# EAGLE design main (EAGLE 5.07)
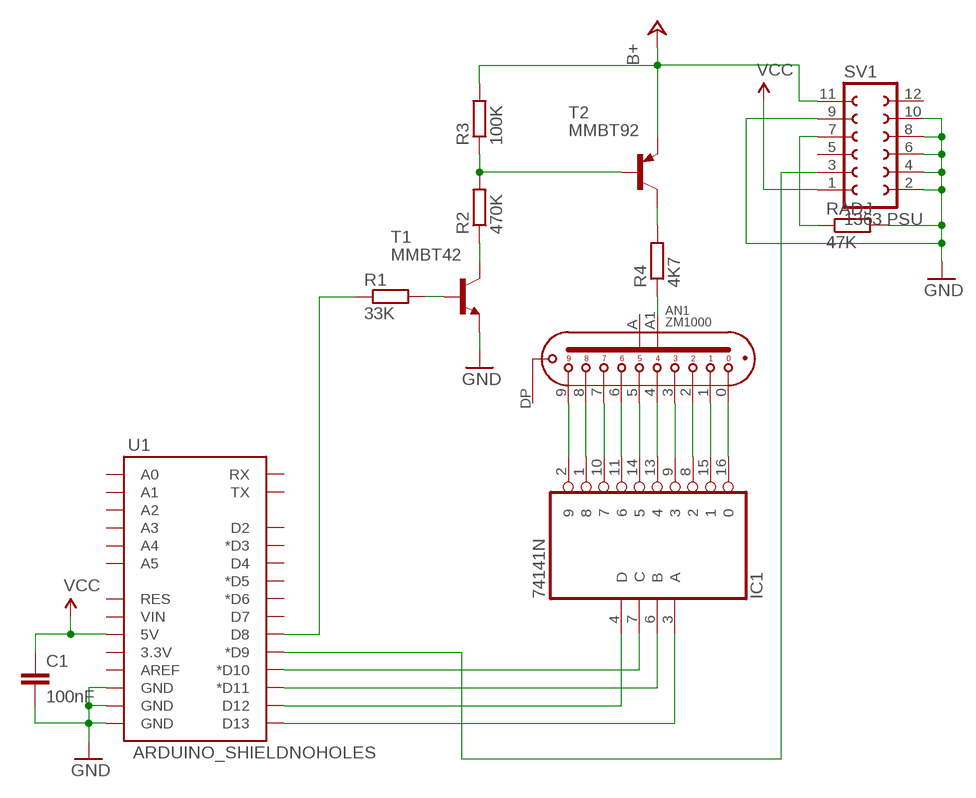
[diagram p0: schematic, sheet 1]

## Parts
AN1  ZM1000  [ZM1000]
C1  100nF  C-EUC0805  [C0805]
IC1  74141N  [DIL16]
R1  33K  R-EU_R0805  [R0805]
R2  470K  R-EU_R0805  [R0805]
R3  100K  R-EU_R0805  [R0805]
R4  4K7  R-EU_R0805  [R0805]
RADJ  47K  R-EU_R0805  [R0805]
SV1  1363 PSU  FE06-2  [FE06-2]
T1  MMBT42  MMBT918LT1-NPN-SOT23-BEC  [SOT23-BEC]
T2  MMBT92  MMBT4403LT1-PNP-SOT23-BEC  [SOT23-BEC]
U1  ARDUINO_SHIELDNOHOLES  [DUEMILANOVE_SHIELD_NOHOLES]

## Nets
+24V: R3.2 SV1.11 T2.E ; supply symbol labelled B+
GND: C1.2 RADJ.2 SV1.2 SV1.4 SV1.6 SV1.8 SV1.9 SV1.10 T1.E U1.GND@0(GND) U1.GND@1(GND) U1.GND@2(GND)
N$1: AN1.A1(A2) R4.1
N$2: SV1.3 U1.D9(*D9)
N$3: R4.2 T2.C
N$4: R2.2 R3.1 T2.B
N$5: R2.1 T1.C
N$6: R1.2 T1.B
N$7: AN1.0 IC1.16
N$8: AN1.1 IC1.15
N$9: AN1.2 IC1.8
N$10: AN1.3 IC1.9
N$11: AN1.4 IC1.13
N$12: AN1.5 IC1.14
N$13: AN1.6 IC1.11
N$14: AN1.7 IC1.10
N$15: AN1.8 IC1.1
N$16: AN1.9 IC1.2
N$17: IC1.3(A) U1.D13
N$18: IC1.4(D) U1.D12
N$19: IC1.6(B) U1.D11(*D11)
N$20: IC1.7(C) U1.D10(*D10)
N$21: R1.1 U1.D8
N$22: RADJ.1 SV1.7
VCC: C1.1 SV1.1 U1.5V
Unconnected: AN1.A(A1) AN1.DP(DPL) SV1.5 SV1.12 U1.3.3V U1.A0 U1.A1 U1.A2 U1.A3 U1.A4 U1.A5 U1.AREF U1.D2 U1.D3(*D3) U1.D4 U1.D5(*D5) U1.D6(*D6) U1.D7 U1.RES U1.RX U1.TX U1.VIN

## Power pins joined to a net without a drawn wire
GND: IC1.12(GND)
VCC: IC1.5(VCC)

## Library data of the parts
AN1 = nixie_tube:ZM1000: Indicator Tube (numeral height 14mm, no filter, side view, long-life typ)
C1 = rcl:C-EU: CAPACITOR, European symbol
IC1 = 74xx-eu:74*141: BCD to decimal DECODER/DRIVER
R1-R4 RADJ = rcl:R-EU_: RESISTOR, European symbol
SV1 = con-lsta:FE06-2: FEMALE HEADER
T1 = transistor:*-NPN-: NPN Transistror BF959 corrected 2008.03.06
T2 = transistor-neu-to92:*-PNP-: PNP Transistror
U1 = zapro:ARDUINO_SHIELD

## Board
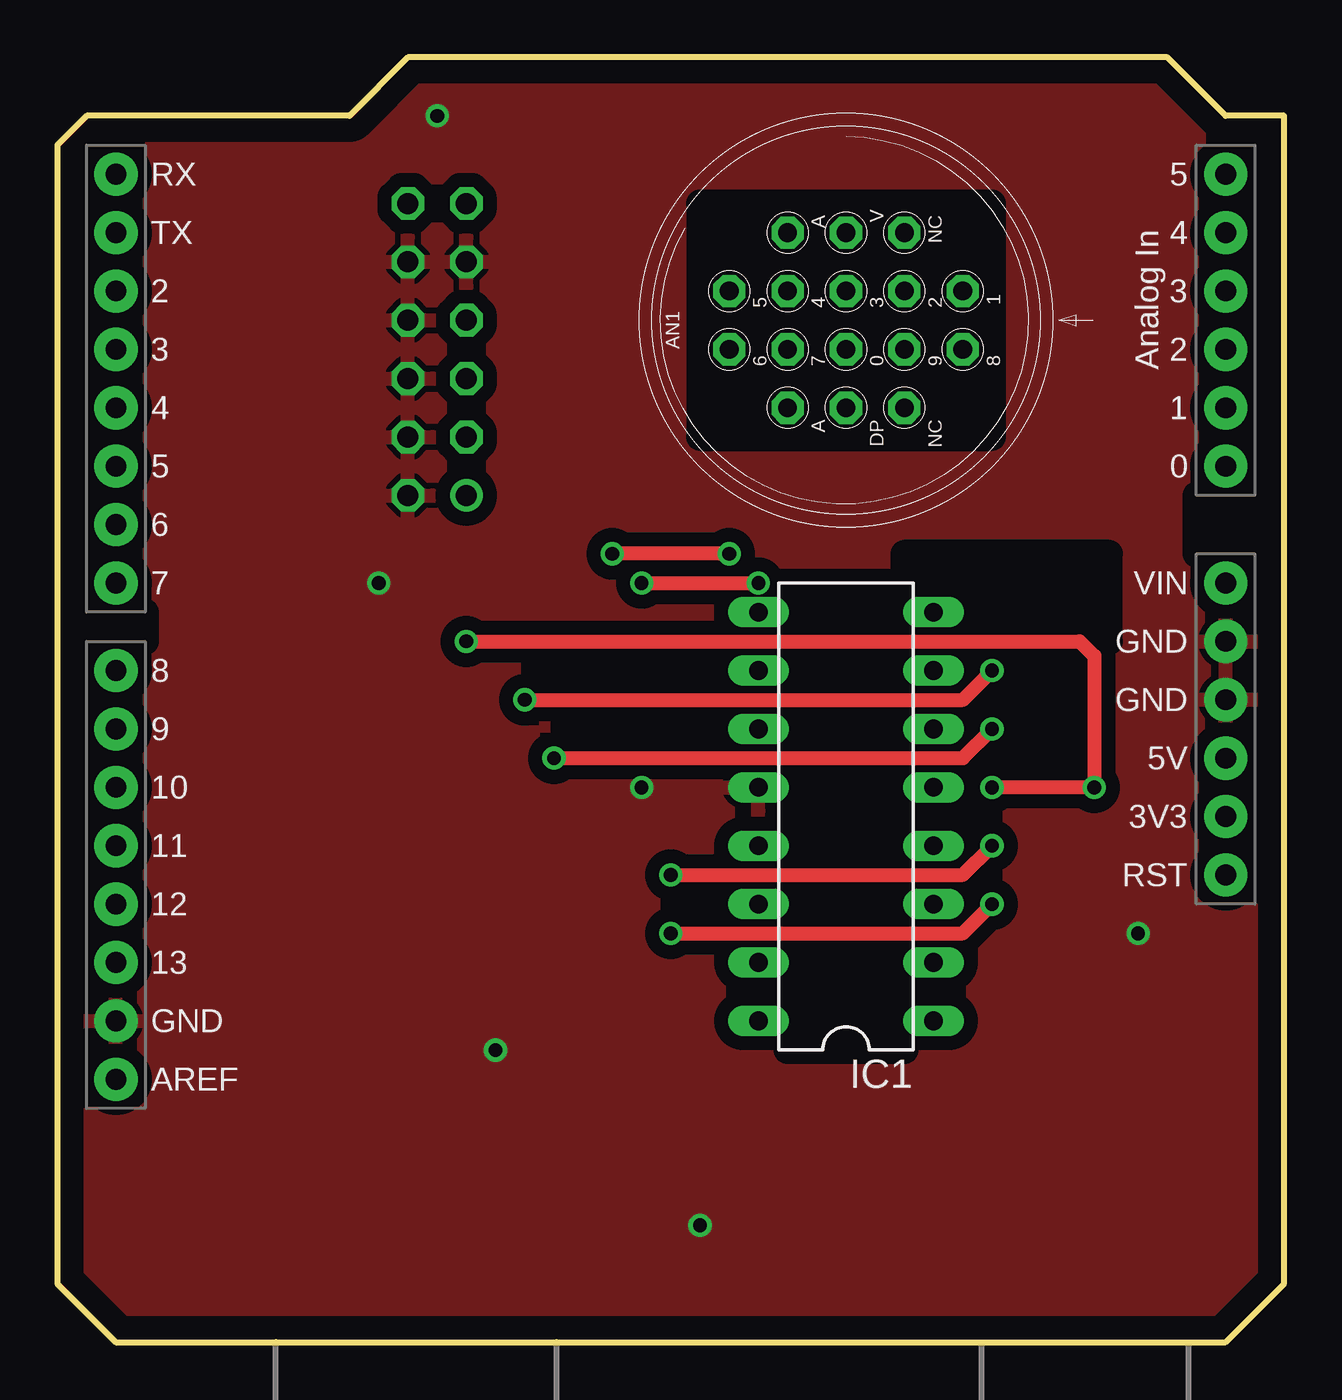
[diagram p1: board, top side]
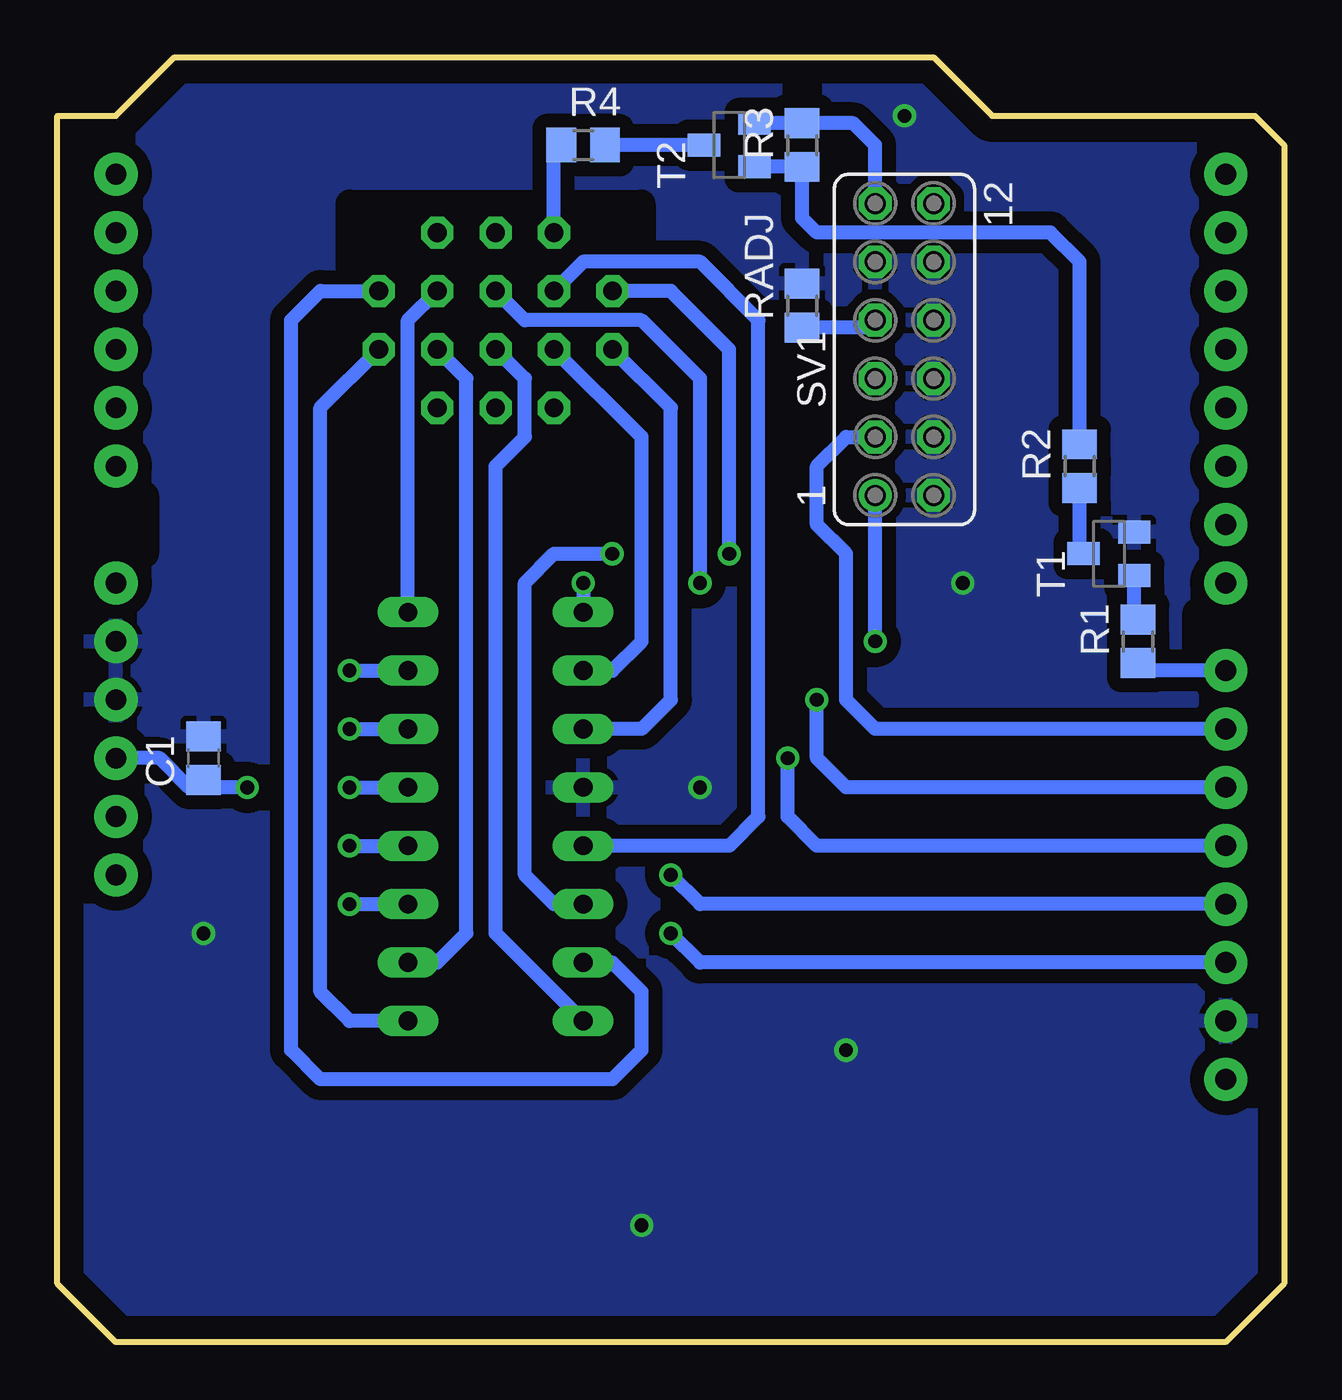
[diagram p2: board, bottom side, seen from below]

Size 53.34 x 55.88 mm. Coordinates in mm from the lower left corner, seen from the top.
Copper layers (1*16): Top 0.035mm / dielectric 1.5mm / Bottom 0.035mm
Design rules "default": minimum track width 10mil, minimum drill 24mil, track to track 8mil, track to pad 8mil, pad to pad 8mil, via to via 8mil, smd to smd 8mil, copper to edge 40mil, drill to drill 8mil, minimum pad ring 10mil, minimum via ring 8mil, stop-mask expansion 4mil, vias tented up to drill 0mil, thermal gap 10mil
tRestrict: area 31.8,12.7 to 36.8,33; area 27.9,39.4 to 40.6,49.5; area 1.3,30.5 to 3.8,31.8; area 49.5,34.3 to 52.1,36.8; area 36.8,30.5 to 45.7,34.3
bRestrict: area 27.9,39.4 to 40.6,49.5; area 1.3,30.5 to 3.8,31.8; area 49.5,34.3 to 52.1,36.8

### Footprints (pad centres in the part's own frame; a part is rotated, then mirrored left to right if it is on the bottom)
ZM1000 = drill 0.813 pad 1.397 octagon: 0 -1.27,0; 1 1.27,-5.08; 2 1.27,-2.54; 3 1.27,0; 4 1.27,2.54; 5 1.27,5.08; 6 -1.27,5.08; 7 -1.27,2.54; 8 -1.27,-5.08; 9 -1.27,-2.54; A -3.81,2.54; A1 3.81,2.54; DP -3.81,0; NC1 3.81,-2.54; NC2 -3.81,-2.54; V 3.81,0
C0805 = smd 1.3 x 1.5: 1 -0.95,0; 2 0.95,0
DIL16 = drill 0.813 long: 1 -8.89,-3.81; 2 -6.35,-3.81; 3 -3.81,-3.81; 4 -1.27,-3.81; 5 1.27,-3.81; 6 3.81,-3.81; 7 6.35,-3.81; 8 8.89,-3.81; 9 8.89,3.81; 10 6.35,3.81; 11 3.81,3.81; 12 1.27,3.81; 13 -1.27,3.81; 14 -3.81,3.81; 15 -6.35,3.81; 16 -8.89,3.81
R0805 = smd 1.3 x 1.5: 1 -0.95,0; 2 0.95,0
FE06-2 = drill 0.914 round: 1 -6.35,1.27 | drill 0.914 octagon: 2 -6.35,-1.27; 3 -3.81,1.27; 4 -3.81,-1.27; 5 -1.27,1.27; 6 -1.27,-1.27; 7 1.27,1.27; 8 1.27,-1.27; 9 3.81,1.27; 10 3.81,-1.27; 11 6.35,1.27; 12 6.35,-1.27
SOT23-BEC = smd 1 x 1.4: B -0.95,-1.1; C 0,1.1; E 0.95,-1.1
DUEMILANOVE_SHIELD_NOHOLES = drill 0.9 pad 1.88 round: 3.3V 50.8,26.67; 5V 50.8,29.21; A0 50.8,41.91; A1 50.8,44.45; A2 50.8,46.99; A3 50.8,49.53; A4 50.8,52.07; A5 50.8,54.61; AREF 2.54,15.24; D2 2.54,49.53; D3 2.54,46.99; D4 2.54,44.45; D5 2.54,41.91; D6 2.54,39.37; D7 2.54,36.83; D8 2.54,33.02; D9 2.54,30.48; D10 2.54,27.94; D11 2.54,25.4; D12 2.54,22.86; D13 2.54,20.32; GND@0 50.8,31.75; GND@1 50.8,34.29; GND@2 2.54,17.78; RES 50.8,24.13; RX 2.54,54.61; TX 2.54,52.07; VIN 50.8,36.83

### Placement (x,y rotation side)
AN1  34.29,44.45 90 top
C1  46.99,25.4 90 bottom
IC1  34.29,22.86 90 top
R1  6.35,30.48 90 bottom
R2  8.89,38.1 90 bottom
R3  20.96,52.07 90 bottom
R4  30.48,52.07 0 bottom
RADJ  20.96,45.09 90 bottom
SV1  16.51,43.18 90 bottom
T1  7.62,34.29 90 bottom
T2  24.13,52.07 90 bottom
U1  0,-3.81 0 top

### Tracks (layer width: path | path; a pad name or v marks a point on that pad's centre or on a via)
+24V
  Bottom 0.61: T2.E R3.2 18.73,53.02 17.78,52.07 SV1.11
GND  (via drill 0.6)
  other vias: 16.51,53.34 46.99,17.78 27.94,5.08 19.05,12.7 13.97,33.02 25.4,24.13
  pour Bottom (isolate 0.61): 1.27,53.34 12.7,53.34 15.24,55.88 48.26,55.88 50.8,53.34 53.34,53.34 53.34,2.54 50.8,0 2.54,0 0,2.54 0,52.07
  pour Top (isolate 0.61): 0,2.54 2.54,0 50.8,0 53.34,2.54 53.34,53.34 50.8,53.34 48.26,55.88 15.24,55.88 12.7,53.34 1.27,53.34 0,52.07
N$1
  Bottom 0.61: AN1.A1 31.75,51.75 R4.1
N$2
  Bottom 0.61: U1.D9 17.78,26.67 19.05,27.94 19.05,34.29 20.32,35.56 20.32,38.1 19.05,39.37 SV1.3
N$3
  Bottom 0.61: T2.C R4.2
N$4
  Bottom 0.61: T2.B R3.1 20.96,48.9 20.32,48.26 10.16,48.26 8.89,46.99 R2.2
N$5
  Bottom 0.61: R2.1 8.89,34.46 T1.C
N$6
  Bottom 0.61: T1.B 6.52,31.6 R1.2
N$7
  Bottom 0.61: AN1.0 33.02,41.91 33.02,39.37 34.29,38.1 34.29,17.78 IC1.16
N$8
  Bottom 0.61: IC1.15 29.21,16.51 27.94,15.24 27.94,12.7 29.21,11.43 41.91,11.43 43.18,12.7 43.18,44.45 41.91,45.72 AN1.1
N$9
  Bottom 0.61: IC1.8 38.1,44.45 AN1.2
N$10  (via drill 0.6)
  Top 0.61: v25.4,33.02 v30.48,33.02
  Bottom 0.61: AN1.3 33.02,44.45 27.94,44.45 25.4,41.91 v25.4,33.02 | v30.48,33.02 IC1.9
N$11
  Bottom 0.61: AN1.4 30.48,46.99 25.4,46.99 22.86,44.45 22.86,22.86 24.13,21.59 IC1.13
N$12  (via drill 0.6)
  Top 0.61: v29.21,34.29 v24.13,34.29
  Bottom 0.61: IC1.14 31.75,19.05 33.02,20.32 33.02,33.02 31.75,34.29 v29.21,34.29 | AN1.5 26.67,45.72 24.13,43.18 v24.13,34.29
N$13
  Bottom 0.61: AN1.6 26.67,40.64 26.67,27.94 27.94,26.67 IC1.11
N$14
  Bottom 0.61: AN1.7 27.94,39.37 27.94,30.48 29.21,29.21 IC1.10
N$15
  Bottom 0.61: AN1.8 41.91,40.64 41.91,15.24 40.64,13.97 IC1.1
N$16
  Bottom 0.61: AN1.9 35.56,41.91 35.56,17.78 36.83,16.51 IC1.2
N$17  (via drill 0.6)
  Top 0.61: v26.67,17.78 39.37,17.78 v40.64,19.05
  Bottom 0.61: U1.D13 25.4,16.51 v26.67,17.78 | v40.64,19.05 IC1.3
N$18  (via drill 0.6)
  Top 0.61: v26.67,20.32 39.37,20.32 v40.64,21.59
  Bottom 0.61: U1.D12 25.4,19.05 v26.67,20.32 | v40.64,21.59 IC1.4
N$19  (via drill 0.6)
  Top 0.61: v21.59,25.4 39.37,25.4 v40.64,26.67
  Bottom 0.61: U1.D11 20.32,21.59 21.59,22.86 v21.59,25.4 | v40.64,26.67 IC1.6
N$20  (via drill 0.6)
  Top 0.61: v20.32,27.94 39.37,27.94 v40.64,29.21
  Bottom 0.61: U1.D10 19.05,24.13 20.32,25.4 v20.32,27.94 | v40.64,29.21 IC1.7
N$21
  Bottom 0.61: U1.D8 6.03,29.21 R1.1
N$22
  Bottom 0.61: RADJ.1 18.1,44.13 SV1.7
VCC  (via drill 0.6)
  Top 0.61: v40.64,24.13 v45.08,24.13 45.08,29.84 44.45,30.48 v17.78,30.48
  Bottom 0.61: v40.64,24.13 IC1.5 | v45.08,24.13 46.67,24.13 C1.1 47.31,24.13 47.62,24.13 48.89,25.4 U1.5V | v17.78,30.48 SV1.1

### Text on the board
tTopText: RX | 5 | TX | 4 | 2 | 3 | 3 | 2 | Analog in | 4 | 1 | 5 | 0 | 6 | 7 | VIN | GND | 8 | GND | 9 | 5V | 10 | 3V3 | 11 | RST | 12 | 13 | GND | AREF
tText: ZM1000 Tester | 2011 Zapro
